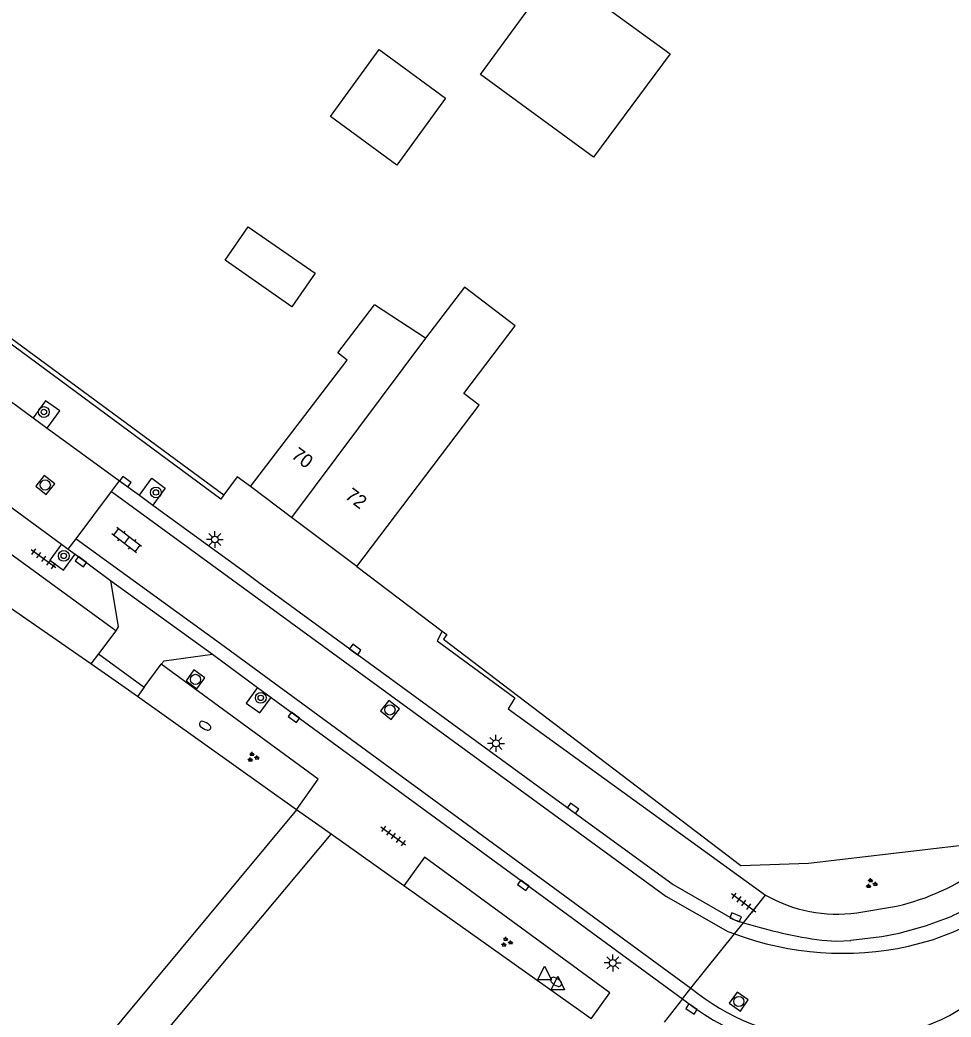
# Model space of a CAD drawing. Extents: x 135990 to 139000, y 393500 to 396000.
# Drawn here: x 136176.2 to 136244.8, y 395330 to 395403.6 of the extents above; entities that cross this region are included whole.
import ezdxf

# ---------------------------------------------------------------- set-up
doc = ezdxf.new("R2010")
doc.units = 0
for name, color, linetype in [('gg-afsc-erfafscheiding', 7, 'Continuous'), ('gg-afsc-hekwerk', 7, 'Continuous'), ('gg-anno-huisnummerreeks BGT', 7, 'Continuous'), ('gg-bbg-bijgebouw', 7, 'Continuous'), ('gg-bbg-gedigitaliseerde bebouwing', 7, 'Continuous'), ('gg-bbg-gedigitaliseerde bijgebouw', 7, 'Continuous'), ('gg-bbg-hoofdgebouw', 7, 'Continuous'), ('gg-bbg-tussenscheiding', 7, 'Continuous'), ('gg-knt-verharding', 7, 'Continuous'), ('gt-grn-groengrens', 7, 'Continuous'), ('gt-grn-vlakafsluiter', 7, 'Continuous'), ('gt-grn-weggrens', 7, 'Continuous'), ('gt-symb-boom', 7, 'Continuous'), ('gt-symb-brandkraan', 7, 'Continuous'), ('gt-symb-groenvak', 7, 'Continuous'), ('gt-symb-klinker verharding', 7, 'Continuous'), ('gt-symb-kolk', 7, 'Continuous'), ('gt-symb-lichtmast', 7, 'Continuous'), ('gt-symb-rioolschacht', 7, 'Continuous'), ('gt-symb-tegel verharding', 7, 'Continuous'), ('gt-symb-waterafsluiter', 7, 'Continuous')]:
    doc.layers.add(name, color=color, linetype=linetype)

# ---------------------------------------------------------------- blocks, each defined once
blk = doc.blocks.new('gt0-BOOM')
at = {"layer": 'gt-symb-boom'}
for radius in [0.4, 0.2]:
    blk.add_circle((0, 0), radius, dxfattribs=at)
blk = doc.blocks.new('gt0-KOLK')
at = {"layer": 'gt-symb-kolk'}
blk.add_lwpolyline([(0, 0), (0.375, 0), (0.375, 0.4), (-0.375, 0.4), (-0.375, 0), (0, 0)], dxfattribs=at)
blk = doc.blocks.new('gt0-KL1')
at = {"layer": 'gt-symb-klinker verharding'}
for p, q in [((-1.15, 0.3), (1.15, 0.3)), ((-1, -0.3), (-1, 0.3)), ((-0.5, 0.3), (-0.5, 0.45)), ((0, -0.3), (0, 0.3)), ((0.5, 0.3), (0.5, 0.45)), ((1, -0.3), (1, 0.3)), ((-1.15, -0.3), (1.15, -0.3)), ((-0.5, -0.45), (-0.5, -0.3)), ((0.5, -0.45), (0.5, -0.3))]:
    blk.add_line(p, q, dxfattribs=at)
blk = doc.blocks.new('gt0-LMAST')
at = {"layer": 'gt-symb-lichtmast'}
for p, q in [((-0.182, 0.173), (-0.447, 0.438)), ((-0.005, 0.246), (-0.005, 0.621)), ((0.172, 0.173), (0.437, 0.438)), ((-0.255, -0.004), (-0.63, -0.004)), ((-0.182, -0.181), (-0.447, -0.446)), ((-0.005, -0.254), (-0.005, -0.629)), ((0.437, -0.446), (0.172, -0.181)), ((0.245, -0.004), (0.62, -0.004))]:
    blk.add_line(p, q, dxfattribs=at)
blk.add_circle((-0.005, -0.004), 0.25, dxfattribs=at)
blk = doc.blocks.new('gt0-TEG1')
at = {"layer": 'gt-symb-tegel verharding'}
for p, q in [((-1.125, 0), (1.125, 0)), ((-0.9, -0.25), (-0.9, 0.25)), ((-0.45, -0.25), (-0.45, 0.25)), ((0, -0.25), (0, 0.25)), ((0.45, -0.25), (0.45, 0.25)), ((0.9, -0.25), (0.9, 0.25))]:
    blk.add_line(p, q, dxfattribs=at)
blk = doc.blocks.new('gt0-RS')
at = {"layer": 'gt-symb-rioolschacht'}
blk.add_lwpolyline([(-0.5, -0.5), (0.5, -0.5), (0.5, 0.5), (-0.5, 0.5)], close=True, dxfattribs=at)
blk.add_circle((0, 0), 0.375, dxfattribs=at)
blk = doc.blocks.new('gt0-BR')
at = {"layer": 'gt-symb-brandkraan'}
for centre, radius, start, end in [((-0.244, 0), 0.206, 107.56694, 252.43307), ((0.599, -2.664), 3, 106.89205, 107.56694), ((0, -0.691), 0.938, 73.10799, 106.89205), ((-0.599, -2.664), 3, 72.43309, 73.10799), ((0.244, 0), 0.206, 287.56695, 72.43309), ((0.599, 2.664), 3, 252.43307, 253.10797), ((0, 0.691), 0.938, 253.10797, 286.89206), ((-0.599, 2.664), 3, 286.89206, 287.56695)]:
    blk.add_arc(centre, radius, start, end, dxfattribs=at)
blk = doc.blocks.new('gt0-GRVAK')
at = {"layer": 'gt-symb-groenvak'}
for p, q in [((-0.11, 0.189), (-0.228, 0.24)), ((-0.182, 0.153), (0.088, 0.153)), ((-0.091, 0.211), (-0.156, 0.322)), ((-0.047, 0.214), (-0.047, 0.393)), ((-0.004, 0.211), (0.061, 0.322)), ((0.015, 0.189), (0.133, 0.24)), ((0.262, -0.052), (0.197, 0.059)), ((0.305, -0.049), (0.305, 0.13)), ((0.349, -0.052), (0.414, 0.059)), ((-0.245, -0.228), (-0.363, -0.177)), ((-0.318, -0.264), (-0.047, -0.264)), ((-0.226, -0.206), (-0.291, -0.095)), ((-0.183, -0.203), (-0.183, -0.024)), ((-0.139, -0.206), (-0.074, -0.095)), ((-0.12, -0.228), (-0.002, -0.177)), ((0.243, -0.074), (0.125, -0.023)), ((0.17, -0.11), (0.441, -0.11)), ((0.368, -0.074), (0.486, -0.023))]:
    blk.add_line(p, q, dxfattribs=at)
blk = doc.blocks.new('gt0-WAFSL')
at = {"layer": 'gt-symb-waterafsluiter'}
for p, q in [((-0.5, -0.333), (0, 0.667)), ((0, 0.667), (0.5, -0.333)), ((0.5, -0.333), (-0.5, -0.333))]:
    blk.add_line(p, q, dxfattribs=at)

msp = doc.modelspace()

# ---------------------------------------------------------------- linework, layer by layer
at = {"layer": 'gg-afsc-erfafscheiding'}
for p, q in [((136171.075, 395383.358), (136191.19, 395368.557)), ((136181.375, 395356.08), (136160.697, 395370.426)), ((136196.555, 395345.334), (136184.824, 395353.669)), ((136199.089, 395343.534), (136196.555, 395345.334)), ((136204.457, 395339.72), (136199.089, 395343.534)), ((136218.27, 395329.906), (136204.457, 395339.72))]:
    msp.add_line(p, q, dxfattribs=at)
for points in [[(136207.631, 395358.241), (136207.39, 395357.903), (136229.306, 395341.209), (136234.303, 395341.382), (136247.714, 395342.965)], [(136184.824, 395353.669), (136183.672, 395354.487), (136181.375, 395356.08)]]:
    msp.add_lwpolyline(points, dxfattribs=at)
at = {"layer": 'gg-afsc-hekwerk'}
for p, q in [((136200.981, 395363.26), (136207.294, 395358.495)), ((136200.981, 395363.26), (136207.294, 395358.495)), ((136207.294, 395358.495), (136207.631, 395358.241)), ((136207.294, 395358.495), (136207.631, 395358.241))]:
    msp.add_line(p, q, dxfattribs=at)
at = {"layer": 'gg-bbg-bijgebouw'}
for points in [[(136203.935, 395392.872), (136199.05, 395396.462), (136202.649, 395401.397), (136207.534, 395397.807), (136203.935, 395392.872)], [(136196.209, 395382.421), (136191.274, 395385.847), (136192.974, 395388.317), (136197.91, 395384.891), (136196.209, 395382.421)]]:
    msp.add_lwpolyline(points, dxfattribs=at)
at = {"layer": 'gg-bbg-gedigitaliseerde bebouwing'}
msp.add_line((136206.056, 395380.114), (136202.291, 395382.56), dxfattribs=at)
msp.add_lwpolyline([(136200.981, 395363.26), (136210.01, 395375.157), (136208.868, 395376.026), (136212.672, 395381.023), (136208.921, 395383.878), (136206.056, 395380.114)], dxfattribs=at)
at = {"layer": 'gg-bbg-gedigitaliseerde bijgebouw'}
msp.add_lwpolyline([(136210.102, 395399.55), (136215.699, 395407.194), (136224.082, 395401.079), (136218.448, 395393.465), (136210.102, 395399.55)], dxfattribs=at)
at = {"layer": 'gg-bbg-hoofdgebouw'}
for p, q in [((136196.184, 395366.879), (136193.161, 395369.16)), ((136200.981, 395363.26), (136196.184, 395366.879))]:
    msp.add_line(p, q, dxfattribs=at)
msp.add_lwpolyline([(136193.161, 395369.16), (136200.281, 395378.49), (136199.591, 395379.02), (136202.291, 395382.56)], dxfattribs=at)
at = {"layer": 'gg-bbg-tussenscheiding'}
msp.add_line((136206.056, 395380.114), (136196.184, 395366.879), dxfattribs=at)
at = {"layer": 'gg-knt-verharding'}
for p, q in [((136170.662, 395378.958), (136177.133, 395374.235)), ((136183.219, 395358.511), (136161.71, 395374.226)), ((136177.133, 395374.235), (136178.171, 395373.478)), ((136178.171, 395373.478), (136183.495, 395369.592)), ((136170.051, 395371.607), (136179.22, 395364.918)), ((136182.895, 395368.792), (136183.495, 395369.592)), ((136183.495, 395369.592), (136184.959, 395368.524)), ((136180.295, 395365.32), (136182.895, 395368.792)), ((136184.959, 395368.524), (136185.952, 395367.799)), ((136185.952, 395367.799), (136192.749, 395362.839)), ((136179.22, 395364.918), (136179.72, 395364.553)), ((136179.72, 395364.553), (136180.295, 395365.32)), ((136180.295, 395365.32), (136190.928, 395357.6)), ((136179.72, 395364.553), (136180.227, 395364.176)), ((136180.227, 395364.176), (136182.831, 395362.243)), ((136192.749, 395362.839), (136193.75, 395362.108)), ((136182.831, 395362.243), (136190.341, 395356.791)), ((136193.75, 395362.108), (136213.487, 395347.705)), ((136183.219, 395358.511), (136181.949, 395356.837)), ((136190.928, 395357.6), (136225.626, 395332.167)), ((136181.949, 395356.837), (136185.317, 395354.363)), ((136190.341, 395356.791), (136193.677, 395354.346)), ((136185.317, 395354.363), (136186.574, 395356.057)), ((136193.677, 395354.346), (136194.681, 395353.61)), ((136194.681, 395353.61), (136216.895, 395337.327)), ((136237.843, 395337.73), (136240.782, 395338.225)), ((136216.895, 395337.327), (136218.402, 395336.222)), ((136218.402, 395336.222), (136225.001, 395331.385)), ((136225.001, 395331.385), (136225.967, 395330.677))]:
    msp.add_line(p, q, dxfattribs=at)
for points in [[(136191.19, 395368.557), (136190.954, 395368.235), (136145.634, 395401.737), (136145.692, 395401.83)], [(136178.171, 395373.478), (136179.097, 395374.747), (136178.048, 395375.488), (136177.133, 395374.235)], [(136241.662, 395335.262), (136243.426, 395335.728), (136244.974, 395336.324), (136246.65, 395337.093), (136248.065, 395337.967), (136249.448, 395338.964), (136252.06, 395341.116), (136260.443, 395347.94), (136276.773, 395361.189), (136288.432, 395370.681), (136290.371, 395372.145)], [(136184.959, 395368.524), (136185.881, 395369.788), (136186.865, 395369.051), (136185.952, 395367.799)], [(136193.161, 395369.16), (136192.166, 395369.889), (136191.19, 395368.557)], [(136182.895, 395368.792), (136223.766, 395338.966), (136228.343, 395336.339), (136228.84, 395336.175)], [(136179.22, 395364.918), (136178.359, 395363.738), (136179.353, 395362.999), (136180.227, 395364.176)], [(136244.677, 395330.146), (136246.407, 395331.176), (136247.825, 395332.138), (136256.87, 395339.47), (136269.908, 395350.04), (136284.063, 395361.561), (136286.705, 395363.693), (136287.63, 395364.416), (136288.573, 395365.101)], [(136182.831, 395362.243), (136183.401, 395358.821), (136183.219, 395358.511)], [(136207.294, 395358.495), (136206.905, 395357.789), (136212.639, 395353.571), (136212.161, 395352.782), (136231.131, 395339.038)], [(136186.574, 395356.057), (136186.784, 395356.321), (136190.341, 395356.791)], [(136196.555, 395345.334), (136198.131, 395347.582), (136186.574, 395356.057)], [(136193.677, 395354.346), (136192.834, 395353.196), (136193.841, 395352.464), (136194.681, 395353.61)], [(136213.487, 395347.705), (136214.484, 395346.978), (136224.311, 395339.806), (136228.841, 395337.206), (136229.5, 395336.995)], [(136218.27, 395329.906), (136219.645, 395331.815), (136205.978, 395341.838), (136204.457, 395339.72)], [(136235.272, 395335.707), (136236.346, 395335.643), (136237.421, 395335.675), (136237.411, 395335.714), (136239.692, 395335.984), (136240.98, 395336.22), (136242.919, 395336.758), (136244.801, 395337.468)]]:
    msp.add_lwpolyline(points, dxfattribs=at)
for centre, radius, start, end in [((136237.041, 395354.777), 16.97, 282.73546, 306.40317), ((136236.389, 395348.143), 10.514, 239.99471, 277.95068), ((136236.99, 395354.889), 19.092, 294.14974, 306.2937), ((136240.332, 395371.958), 36.603, 252.78703, 262.05448), ((136236.819, 395357.733), 22.987, 249.6908, 282.16337), ((136236.712, 395345.862), 17.62, 231.01198, 296.87702), ((136236.884, 395346.115), 18.908, 234.73328, 308.8379)]:
    msp.add_arc(centre, radius, start, end, dxfattribs=at)
at = {"layer": 'gt-grn-groengrens'}
for p, q in [((136181.949, 395356.837), (136181.375, 395356.08)), ((136185.317, 395354.363), (136184.824, 395353.669))]:
    msp.add_line(p, q, dxfattribs=at)
at = {"layer": 'gt-grn-vlakafsluiter'}
for points in [[(136196.555, 395345.334), (136153.746, 395293.901), (136136.965, 395308.571), (136138.775, 395310.131), (136126.192, 395321.407), (136139.516, 395336.608), (136134.358, 395341.535), (136160.697, 395370.426)], [(136182.483, 395268.442), (136155.918, 395291.987), (136199.089, 395343.534)]]:
    msp.add_lwpolyline(points, dxfattribs=at)
at = {"layer": 'gt-grn-weggrens'}
for p, q in [((136229.5, 395336.995), (136231.131, 395339.038)), ((136228.84, 395336.175), (136229.5, 395336.995)), ((136225.626, 395332.167), (136228.84, 395336.175)), ((136225.001, 395331.385), (136225.626, 395332.167)), ((136225.001, 395331.385), (136223.641, 395329.661))]:
    msp.add_line(p, q, dxfattribs=at)

# ---------------------------------------------------------------- block references
at = {"layer": 'gt-symb-boom'}
for p in [(136177.917, 395374.66), (136186.177, 395368.728), (136179.387, 395364.049), (136193.912, 395353.58)]:
    msp.add_blockref('gt0-BOOM', p, dxfattribs=at)
at = {"layer": 'gt-symb-brandkraan'}
for p, rotation in [((136189.8, 395351.526), -29.126912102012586), ((136215.685, 395332.633), -32.95900987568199)]:
    msp.add_blockref('gt0-BR', p, dxfattribs=dict(at, rotation=rotation))
at = {"layer": 'gt-symb-groenvak'}
for p in [(136193.321, 395349.2), (136238.917, 395339.878), (136212.023, 395335.564)]:
    msp.add_blockref('gt0-GRVAK', p, dxfattribs=at)
at = {"layer": 'gt-symb-klinker verharding', "rotation": 142.63746931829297}
msp.add_blockref('gt0-KL1', (136184.019, 395365.206), dxfattribs=at)
at = {"layer": 'gt-symb-kolk'}
for p, rotation in [((136183.804, 395369.353), -36.09056723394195), ((136180.762, 395363.793), 143.90943276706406), ((136200.754, 395356.986), -36.09056723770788), ((136196.467, 395352.315), 143.74924417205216), ((136216.816, 395345.277), -36.09056723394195), ((136213.385, 395339.924), 143.70304105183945), ((136228.841, 395337.206), -22.461175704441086), ((136225.779, 395330.804), 145.96047544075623)]:
    msp.add_blockref('gt0-KOLK', p, dxfattribs=dict(at, rotation=rotation))
at = {"layer": 'gt-symb-lichtmast'}
for p in [(136190.526, 395365.262), (136211.255, 395350.229), (136219.865, 395334.033)]:
    msp.add_blockref('gt0-LMAST', p, dxfattribs=at)
at = {"layer": 'gt-symb-rioolschacht'}
for p, rotation in [((136178.022, 395369.277), 141.2507230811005), ((136189.096, 395354.943), -36.09056723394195), ((136203.434, 395352.691), 141.45653728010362), ((136229.15, 395331.184), 144.56219853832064)]:
    msp.add_blockref('gt0-RS', p, dxfattribs=dict(at, rotation=rotation))
at = {"layer": 'gt-symb-tegel verharding'}
for p, rotation in [((136177.889, 395363.833), 143.78311535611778), ((136203.681, 395343.392), 143.82935586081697), ((136229.51, 395338.451), 143.62293247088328)]:
    msp.add_blockref('gt0-TEG1', p, dxfattribs=dict(at, rotation=rotation))
at = {"layer": 'gt-symb-waterafsluiter'}
for p in [(136214.835, 395333.116), (136215.807, 395332.392)]:
    msp.add_blockref('gt0-WAFSL', p, dxfattribs=at)

# ---------------------------------------------------------------- texts
at = {"layer": 'gg-anno-huisnummerreeks BGT'}
for s, p in [('70', (136196.088, 395371.336)), ('72', (136200.053, 395368.345))]:
    msp.add_text(s, height=1, rotation=323, dxfattribs=at).set_placement(p)

doc.saveas('drawing.dxf')
